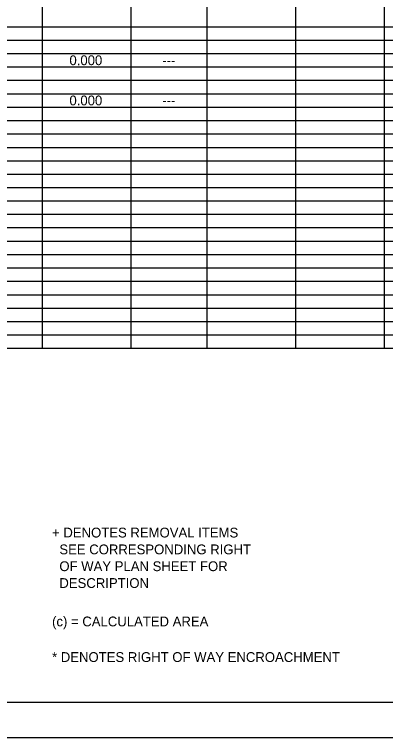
# Model space of a CAD drawing. Extents: x 0 to 34, y 0 to 22.
# Drawn here: x 19.78 to 25.07, y 0 to 10.32 of the extents above; entities that cross this region are included whole.
import ezdxf

# ---------------------------------------------------------------- set-up
doc = ezdxf.new("R2010")
doc.units = 0
for name, color, linetype in [('Default', 7, 'Continuous'), ('SH_Border', 7, 'Continuous'), ('SH_Cut_Line', 7, 'Continuous'), ('SH_Text', 7, 'Continuous')]:
    doc.layers.add(name, color=color, linetype=linetype)

msp = doc.modelspace()

# ---------------------------------------------------------------- linework, layer by layer
at = {"layer": 'Default'}
for p, q in [((20.176, 5.554), (20.176, 16.637)), ((21.442, 5.554), (21.442, 16.637)), ((22.526, 5.554), (22.526, 16.637)), ((25.057, 5.554), (25.057, 16.637)), ((23.792, 5.554), (23.792, 16.446)), ((1.5, 10.14), (31.964, 10.14)), ((1.5, 9.949), (31.964, 9.949)), ((1.5, 9.758), (31.964, 9.758)), ((1.5, 9.567), (31.964, 9.567)), ((1.5, 9.376), (31.964, 9.376)), ((1.5, 9.185), (31.964, 9.185)), ((1.5, 8.993), (31.964, 8.993)), ((1.5, 8.802), (31.964, 8.802)), ((1.5, 8.611), (31.964, 8.611)), ((1.5, 8.42), (31.964, 8.42)), ((1.5, 8.229), (31.964, 8.229)), ((1.5, 8.038), (31.964, 8.038)), ((1.5, 7.847), (31.964, 7.847)), ((1.5, 7.656), (31.964, 7.656)), ((1.5, 7.465), (31.964, 7.465)), ((1.5, 7.274), (31.964, 7.274)), ((1.5, 7.082), (31.964, 7.082)), ((1.5, 6.891), (31.964, 6.891)), ((1.5, 6.7), (31.964, 6.7)), ((1.5, 6.509), (31.964, 6.509)), ((1.5, 6.318), (31.964, 6.318)), ((1.5, 6.127), (31.964, 6.127)), ((1.5, 5.936), (31.964, 5.936)), ((1.5, 5.745), (31.964, 5.745)), ((1.5, 5.554), (31.964, 5.554))]:
    msp.add_line(p, q, dxfattribs=at)
at = {"layer": 'SH_Border'}
msp.add_lwpolyline([(1.5, 21.5), (33.5, 21.5), (33.5, 0.5), (1.5, 0.5)], close=True, dxfattribs=at)
at = {"layer": 'SH_Cut_Line'}
msp.add_lwpolyline([(0, 0), (34, 0), (34, 22), (0, 22)], close=True, dxfattribs=at)

# ---------------------------------------------------------------- texts
at = {"layer": 'Default'}
for s, p in [('0.000', (20.561, 9.592)), ('---', (21.886, 9.592)), ('0.000', (20.561, 9.019)), ('---', (21.886, 9.019)), ('(c) = CALCULATED AREA', (20.313, 1.586)), ('* DENOTES RIGHT OF WAY ENCROACHMENT', (20.313, 1.078))]:
    msp.add_text(s, height=0.14, dxfattribs=at).set_placement(p)
at = {"layer": 'SH_Text'}
for s, p in [('+ DENOTES REMOVAL ITEMS', (20.313, 2.854)), ('  SEE CORRESPONDING RIGHT', (20.313, 2.614)), ('  OF WAY PLAN SHEET FOR', (20.313, 2.374)), ('  DESCRIPTION', (20.313, 2.134))]:
    msp.add_text(s, height=0.14, dxfattribs=at).set_placement(p)

doc.saveas('drawing.dxf')
